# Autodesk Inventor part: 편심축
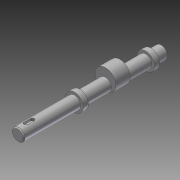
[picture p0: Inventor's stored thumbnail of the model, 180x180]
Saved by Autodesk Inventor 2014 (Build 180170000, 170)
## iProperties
Created: 2016-02
Part Number: 편심축
Material: 강철, 연강
Document SubType Name: Modeling
Designer: mduedu
Density: 1 g/cm^3
Appearance: 강철
Author: mduedu
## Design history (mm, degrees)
sketch "스케치1"
  geometry: C1 r 6 at (0, 0); 1 further point
  constraints: 1 centre point, 1 coincident
  dimensions: "d0" = 12 diameter of C1
extrude "돌출1" new body sketch "스케치1" distance "d1" = 140; taper "d2" = 0 deg
chamfer "모따기1" distance "d3" = 1; stored, may be unused: second distance "d4" = 2, angle "d5" = 45 deg
node "작업 평면1"
sketch "스케치2"
  geometry: C1 r 10 at (0, 4); C2 r 6 at (0, 0) reference; 1 further point
  constraints: 1 centre point, 1 tangent, 1 vertical alignment
  dimensions: "d7" = 20 diameter of C1
extrude "돌출2" join sketch "스케치2" stored distance "d8" = 14; taper "d9" = 0 deg
node "작업 평면2"
sketch "스케치3"
  geometry: C1 r 8.5 at (0, 0); 1 further point
  constraints: 1 centre point, 1 coincident
  dimensions: "d12" = 17 diameter of C1
extrude "돌출3" join sketch "스케치3" distance "d13" = 5; taper "d14" = 0 deg
node "작업 평면3"
sketch "스케치4"
  geometry: L1 (-5, 140)-(5, 140) reference; L2 (0, 140)-(0, 0); L3 (-2, 132)-(-2, 126); L4 (2, 126)-(2, 132); A1 r 2 centre (0, 132) between (2, 132) and (-2, 132); A2 r 2 centre (0, 126) between (-2, 126) and (2, 126)
  constraints: 6 end point, 4 point on circle, 4 tangent, 2 centre point, 2 point on line, 1 midpoint, 1 parallel, 1 perpendicular
  dimensions: "d15" = 4 distance between parallel lines of L3 L4; "d17" = 6 distance edge to line of A1 L1; "d18" = 10 dimension on A2 A1
extrude "돌출4" cut sketch "스케치4" distance "d19" = 2.5; taper "d20" = 0 deg
sketch "스케치5"
  geometry: L1 (6, 55)-(6, 139) reference; L2 (-6, 55)-(-6, 139) reference; L3 (6, 115)-(-6, 115); L4 (-5, 140)-(5, 140) reference; L5 (6, 116.5)-(4.5, 115); L6 (6, 116.5)-(6, 115); L7 (4.5, 115)-(6, 115); 1 further point
  constraints: 8 end point, 4 point on line, 2 collinear, 1 perpendicular
  dimensions: "d21" = 25 distance between parallel lines of L3 L4; "d22" = 3 diameter of L5.start L3; "d24" = 45 deg angle of L3 L5
revolve "회전1" sketch "스케치5" stored, may be unused: angle "d25" = 90 deg
sketch "스케치6"
  geometry: L1 (6, 116.5)-(4.5, 115) reference; L2 (6, 113.5)-(4.5, 115) reference; 2 further points
  constraints: 1 coincident
node "작업 평면4"
sketch "스케치7"
  geometry: C1 r 8.5 at (0, -4); 1 further point
  constraints: 1 centre point, 1 coincident
  dimensions: "d27" = 17 diameter of C1
extrude "돌출5" join sketch "스케치7" distance "d29" = 5; taper "d30" = 0 deg
node "작업점1"
node "솔리드1"
other parameters: "d6" = -48, "d11" = -11
